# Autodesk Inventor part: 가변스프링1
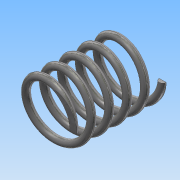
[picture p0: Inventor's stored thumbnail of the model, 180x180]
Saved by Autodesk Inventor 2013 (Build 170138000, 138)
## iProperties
Created: 2018-10
Part Number: 가변스프링1
Material: 스테인리스강
Document SubType Name: Modeling
Designer: Administrator
Density: 8.08 g/cm^3
Mass: 6.27535 g
Surface Area: 15.7599 cm^2
Volume: 0.776652 cm^3
Author: Administrator
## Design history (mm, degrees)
sketch "스케치1"
  geometry: L1 (0, 0)-(8, 0); L2 (0, 0)-(0, 25.52); L3 (0, 25.52)-(8, 25.52); C1 r 1 at (8, 0)
  constraints: 6 end point, 2 perpendicular, 1 centre point, 1 coincident, 1 horizontal
  dimensions: "d0" = 8 distance of L1.start L1.end; "d1" = 25.5198 distance of L1.start L2.end (derived); "d2" = 8 distance of L2.end L3.end; "d3" = 2 diameter of C1
feature "코일1" sketch "스케치1" pitch "d4" = 10; turns "d6" = 5; dims "d5" = 25.5198 (= d1), "d7" = 0, angle "d8" = 90 deg, angle "d9" = 90 deg, "d10" = 0, "d11" = 0
sketch "스케치2"
  geometry: L1 (25.52, 9.5)-(0, 9.5); L2 (0, 9.5)-(0, -9.5); L3 (0, -9.5)-(25.52, -9.5); L4 (25.52, -9.5)-(25.52, 9.5); 2 further points
  constraints: 8 end point, 2 parallel, 1 coincident, 1 horizontal, 1 midpoint, 1 perpendicular
  dimensions: "d12" = 25.5198 distance from line of point (0, 0) L4 (derived); "d13" = 19 distance between parallel lines of L3 L1
extrude "돌출1" sketch "스케치2" stored distance "d14" = 0; taper "d15" = 0 deg
node "솔리드1"
